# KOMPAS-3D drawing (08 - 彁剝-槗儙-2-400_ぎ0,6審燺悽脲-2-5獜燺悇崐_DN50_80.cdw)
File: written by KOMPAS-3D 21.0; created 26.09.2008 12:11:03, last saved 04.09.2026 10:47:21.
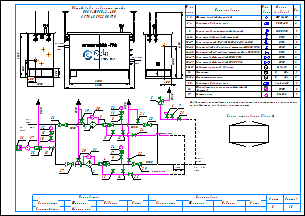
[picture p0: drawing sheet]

Sheets 1-2: A3, landscape

Document properties: Наименование: Макро:21; Автор: RaskoAdmin; Форматы листов документа: 2xA3; Полное имя файла: \\UR38nt01\Departments\КТО\КБ ПУРДГ\Заявки\Прайс-лист на типовые шкафы ГРПШ\ПРДГ_стандарт_20_03_2026\ПРДГ с РДНК\ПРДГ-ШУГО-2-400_до0,6МПа_Рвых-2-5кПа_РДНК_DN50_80.cdw

Title block, sheet 1: Наименование: Пункт учета газа / ПУГ-Ш-400-Р / ЛГТИ.485922.001ТУ; designation: ЛГТИ.03.4411141; sheet number: 1; Количество листов документа: 2; organisation: ООО "ЭЛЬСТЕР Газэлектроника"; Форматы листов документа: A3; stored path: C:\Рабочие документы\Компас\ПУГ\Схема.cdw; Разработал: Устинов; Проверил: Кошкин; Утвердил: Кошкин
Title block, sheet 2: sheet number: 2; stored path: D:\Рабочие документы\Заявки\ПУРДГ\ПУРДГ-ШУЭО-2-100-Р 4411220.cdw; designation, second copy: ЛГТИ.03.4411141-

Views: Вид 1, Вид 2
Referenced files: wcvoit.frw
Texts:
  Normal
  Вход
  газа
  PDI
  Выход
  Р=     кПа
  DN80
  DN50
  DN20
  Импульс DN15
  ≥5DN
  HYSWLongFangSong
  № на
  схеме
  Усл.
  обозн.
  Марка
  (модель)
  Кол.
  Фильтр газовый фланцевый
  ФГ 16-50
  Регулятор давления газа
  РДНК-50
  Клапан предохранительный сбросной
  КПС DN20
  Кран шаровой газовый латунный
  DN15
  Кран кнопочный VE-РАСКО-НЗ-1,6-G1/2-М20
  Кран шаровой "под приварку" штуцерный DN20 PN16
  Кран шаровой "под приварку" штуцерный п/п DN15 PN16
  Кран шаровой фланцевый DN50 PN16
  Кран шаровой фланцевый DN80 PN16
  Индикатор перепада давления
  Delta 15
  Манометр
  Манометр-напоромер
  0...     МПа
  0...     кПа
  Обогреватель газогорелочный шкафной
  (Эльтон")
  Счетчик газа
  Venio-A-15
  ОГШН
  BK-G1,6
  Общий вид и габариты шкафа
  ПРДГ-ШУГО-2-400
  Выход газа
  Вход газа
  Схема открывания дверей
  logo-rasko-ge.png
  Предприятие изготовитель может заменять комплектующие на аналогичные,
  не ухудшающие заявленных характеристик.
  Р=        МПа
  Должность
  Конструктор
  Фамилия
  Подпись
  Дата
  Согласовано
  Максимкин
  Лист
  Листов
  POLYLINE_STYLE_0.18_RGB_0_0_0
  POLYLINE_STYLE_0.50_RGB_0_0_0
  POLYLINE_STYLE_0.34_RGB_0_0_0
  PHANTOM_RGB_0_0_0_SC_1_THICK_0.18
  K5LT_THIN_RGB_0_0_0_THICK_0.18
  K5LT32769_RGB_0_0_0_THICK_0.18
  K5LT12_RGB_0_0_0_SC_1_THICK_0.18
  K5LT_DASHED_RGB_0_0_0_SC_1_THICK_0.18
  ACISOTGL_RGB_0_0_0_SC_0.8_THICK_0.25
  CONTINUOUS_RGB_0_127_31_THICK_0.3
  CONTINUOUS_RGB_0_0_255_THICK_0.35
  CONTINUOUS_RGB_255_0_0_THICK_0.35
  POLYLINE_STYLE_0.25_RGB_0_0_0
  CONTINUOUS_RGB_0_0_0_THICK_0.5
  POLYLINE_STYLE_0.35_RGB_0_0_255
  CONTINUOUS_RGB_0_0_0_THICK_0.4
  CONTINUOUS_RGB_0_0_0_THICK_0.35
  Без оформления
Dimensions and other numbers on the sheet: 1; 2; 3; 4; 5; 10; 27; 28; 29; 23; 8; 12; 18; 19; 20; 21; 22; 25; 24; 30; 31; 15; 16; 35; 36; 26; 6; 7; 11; 14; 13; 33; 1, 2; 3, 4; 6-14; 9; 15-17; 18-23; 24-25; 26-27; 28-29; 30-31; 32; 33-34; 37; 400; 1050; 500; 305; 2300; 1565; 2600; 17; 34; 1000; 4130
